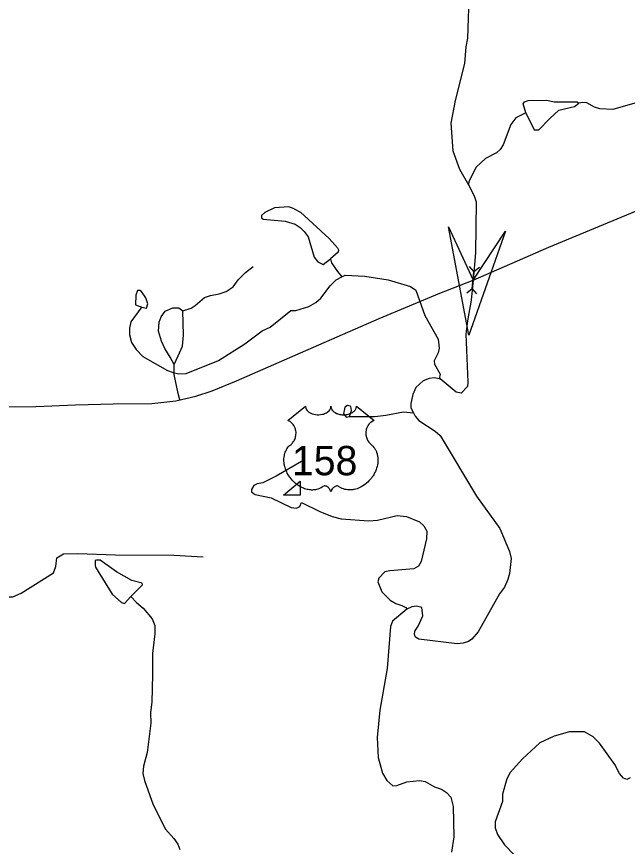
# Model space of a CAD drawing. Extents: x 2056842 to 2160602, y 826753 to 1016856.
# Drawn here: x 2086830 to 2091249, y 929883 to 935892 of the extents above; entities that cross this region are included whole.
import ezdxf

# ---------------------------------------------------------------- set-up
doc = ezdxf.new("R2010")
doc.units = 0
for name, color, linetype in [('Exist Hydrographic Creek Single Shore', 7, 'Continuous'), ('Exist Hydrographic Misc Water Feature', 7, 'Continuous'), ('Exist Hydrographic Pond Under 1500 Sq Ft', 7, 'Continuous'), ('Exist Road Non-System Type 51', 7, 'Continuous'), ('Exist Road Primary US Attributed', 7, 'Continuous'), ('Exist Road Primary US Shield CELL', 7, 'Continuous'), ('Exist Road Primary US Shield Number Label', 7, 'Continuous'), ('Exist Road Secondary Structure Culvert Attributed CELL', 7, 'Continuous'), ('Exist Road Secondary Structure Culvert CELL', 7, 'Continuous')]:
    doc.layers.add(name, color=color, linetype=linetype)

msp = doc.modelspace()

# ---------------------------------------------------------------- linework, layer by layer
at = {"layer": 'Exist Hydrographic Creek Single Shore'}
for points in [[(2090123.3, 936204), (2090103.7, 936095.8), (2090092.6, 935735.7), (2090078.8, 935671.7), (2090069.4, 935551.8), (2090002.2, 935283.5), (2089970.5, 935119.4), (2089985.4, 934919.6), (2090033.5, 934787.7), (2090100.1, 934673.7)], [(2092247.7, 935376.8), (2092095.6, 935418.2), (2091939.7, 935413.8), (2091799.9, 935425.4), (2091739.6, 935441.1), (2091683.6, 935436.9), (2091587.8, 935394.6), (2091484.1, 935326.3), (2091420.1, 935298.1), (2091142.5, 935219.3), (2091050.4, 935223), (2091010.4, 935234.9), (2090954.2, 935266.6), (2090926.3, 935270.5), (2090898.3, 935264.5)], [(2090514.6, 935195.3), (2090494.3, 935259.3), (2090504.3, 935273.2), (2090530.2, 935283.4), (2090666.3, 935285.7), (2090718.2, 935273.9), (2090884.3, 935274.4), (2090898.3, 935264.5)], [(2090686.6, 935153.9), (2090752.5, 935214), (2090866.5, 935240.4), (2090898.3, 935264.5)], [(2090514.6, 935195.3), (2090440.6, 935159.1), (2090406.7, 935111), (2090349.3, 934962.8), (2090327.4, 934928.7), (2090301.3, 934904.6), (2090221.6, 934864.4), (2090155.8, 934802.2), (2090102.2, 934698), (2090100.2, 934674)], [(2090514.6, 935195.3), (2090574.9, 935071.5), (2090606.9, 935071.6), (2090686.6, 935153.9)], [(2090100.1, 934673.7), (2090140.4, 934594.1), (2090154.3, 934550.2), (2090149.8, 934180.5), (2090132.3, 933982.4), (2090117.5, 933837), (2090091.1, 933687.9), (2090079.3, 933592), (2090094.3, 933243.9), (2090092.7, 933212.1), (2090046.7, 933163.8), (2090010.8, 933171.8), (2089894.4, 933269.3), (2089886.5, 933269.2)], [(2089182.4, 934007.2), (2089206.4, 934019.3), (2089350.3, 934011.7), (2089518.5, 933984.2), (2089678.6, 933936.8), (2089718.6, 933910.9), (2089783.2, 933727.1), (2089879.8, 933555.4), (2089888, 933489.5), (2089880, 933457.5), (2089850.2, 933399.3), (2089852.3, 933375.3), (2089894.5, 933301.4), (2089886.5, 933269.4)], [(2089886.5, 933269.2), (2089850.5, 933275.2), (2089814.4, 933271), (2089770.4, 933254.8), (2089718.5, 933206.7), (2089696.8, 933154.6), (2089681, 933090.7), (2089681, 933058.8), (2089701.3, 933022.6)], [(2089701.3, 933022.6), (2089713.2, 932998.8), (2089739.5, 932966.7), (2089857.6, 932889.1), (2089893.7, 932857.2), (2090156.9, 932418.3), (2090325.7, 932184.8), (2090396.4, 932018.9), (2090408.4, 931967.1), (2090396.7, 931859.1), (2090384.9, 931815), (2090359.2, 931758.8), (2090323.1, 931712.6), (2090168.1, 931436.3), (2090124.3, 931384), (2090098.4, 931366.2), (2090060.4, 931353.9), (2090016.3, 931349.9), (2089740.4, 931382.8), (2089716.4, 931396.8), (2089708.3, 931417), (2089712.1, 931440.8), (2089736.1, 931477.1), (2089769.8, 931551.2), (2089761.6, 931613.1), (2089723.7, 931621.1), (2089689.5, 931616.9), (2089653.7, 931600.5)], [(2088891.4, 932372.4), (2089023.7, 932306.8), (2089113.9, 932271.1), (2089177.9, 932255.4), (2089377.8, 932240), (2089441.8, 932244.2), (2089583.7, 932278.5), (2089651.7, 932270.8), (2089745.9, 932233.1), (2089776, 932205.2), (2089798.1, 932165.2), (2089796.1, 932109.3), (2089756.7, 931945.1), (2089736.8, 931913), (2089704.9, 931893), (2089531, 931878.5), (2089494.9, 931870.3), (2089451.2, 931826.2), (2089443.2, 931798.2), (2089471.5, 931726.2), (2089531.6, 931666.4), (2089573.6, 931642.7), (2089617.7, 931626.8), (2089645.8, 931612.8), (2089653.8, 931600.8)], [(2089653.7, 931600.5), (2089549.9, 931514.4), (2089535.9, 931474.3), (2089510.9, 931170.4), (2089458.1, 930870.2), (2089438.5, 930670.1), (2089445, 930526), (2089477.4, 930412.1), (2089507.5, 930360.3), (2089551.7, 930320.3), (2089579.6, 930324.7), (2089653.7, 930350.7), (2089745.4, 930360.9), (2089785.6, 930353.2), (2089853.7, 930313.4), (2089903.6, 930297.6), (2089939.8, 930273.5), (2089971.9, 930239.7), (2089987.9, 930171.8), (2089992.9, 929951.9), (2089977.1, 929840)], [(2091269.3, 930379.8), (2091245.4, 930367.9), (2091221.3, 930377.6), (2091191.2, 930411.6), (2091159.1, 930475.6), (2091046.4, 930629.2), (2091000.5, 930677.1), (2090938.2, 930712.9), (2090830.3, 930712.5), (2090718.4, 930680), (2090614.7, 930631.6), (2090490.9, 930517.4), (2090401.2, 930417.2), (2090377.3, 930373.1), (2090345.8, 930260.9), (2090344.1, 930209), (2090292.4, 930060.8), (2090292.5, 930016.8), (2090308.6, 929968.9), (2090360.8, 929893), (2090433.1, 929819.3)]]:
    msp.add_lwpolyline(points, dxfattribs=at)
at = {"layer": 'Exist Hydrographic Misc Water Feature'}
for points in [[(2088836.9, 934500.1), (2088798.7, 934514), (2088694.8, 934505.7), (2088624.8, 934473.5), (2088601.1, 934451.4), (2088601.1, 934433.4), (2088612.9, 934425.4), (2088773.1, 934409.9), (2088845.1, 934388.1), (2088881.4, 934364.3), (2088909.2, 934334.4)], [(2088836.9, 934500.1), (2088883, 934476.3), (2089091.5, 934284.9), (2089151.6, 934217.1), (2089157.8, 934203.1), (2089155.7, 934185.2), (2089102, 934136.9)], [(2088909.2, 934334.4), (2088939.4, 934296.4), (2088983.9, 934148.6), (2089008.1, 934116.6), (2089048.1, 934096.8), (2089102, 934136.9)], [(2089102, 934136.9), (2089107.9, 934108.9), (2089152.2, 934045.2), (2089182.4, 934007.2)], [(2087735.1, 933788.7), (2087657.4, 933680.5), (2087645.7, 933636.5), (2087645.7, 933586.4), (2087661.9, 933532.5), (2087696, 933480.6), (2087744.3, 933430.7), (2087920.5, 933329.3), (2087962.5, 933313.4), (2088004.8, 933305.5), (2088056.6, 933307.8), (2088290.4, 933400.5), (2088481.9, 933521), (2088607.6, 933615.5), (2088665.6, 933643.7), (2088815.1, 933764.1), (2088851.2, 933764.2), (2088945.1, 933792.5), (2088995, 933820.6), (2089030.8, 933852.8), (2089098.5, 933941), (2089142.4, 933985.1), (2089182.4, 934007.2)], [(2089239.6, 932995.5), (2089421.5, 932996), (2089501.4, 933004.3), (2089629.4, 933030.7), (2089701.4, 933022.9)], [(2088890.6, 932670.4), (2088708.9, 932563.9), (2088611.1, 932515.5), (2088571.1, 932507.5), (2088547.1, 932495.3), (2088529.1, 932467.3), (2088529.3, 932451.3), (2088541.4, 932441.3)], [(2088541.4, 932441.3), (2088555.3, 932431.4), (2088671.4, 932407.7), (2088815.5, 932336.1), (2088855.5, 932332.4), (2088879.5, 932344.3), (2088891.4, 932372.4)], [(2087553.2, 931870.3), (2087434.9, 931955.9), (2087407, 931955.8), (2087398.8, 931951.8), (2087399, 931917.7)], [(2087399, 931917.7), (2087401.1, 931903.8), (2087521.7, 931710.1), (2087587.9, 931648.4), (2087609.8, 931640.5), (2087657.6, 931692.6)], [(2087657.6, 931692.6), (2087741.5, 931776.9), (2087737.4, 931788.9), (2087663.4, 931808.6), (2087553.2, 931870.3)], [(2087657.6, 931692.6), (2087697.8, 931648.7), (2087746, 931608.8), (2087810.2, 931531.1), (2087830.3, 931483.1), (2087830.5, 931423.1), (2087813, 931279.1), (2087813.5, 931127.1), (2087808.1, 930927.1), (2087798.3, 930851.1), (2087800.5, 930775.1), (2087775.1, 930563.1), (2087747.6, 930463), (2087743.7, 930410.9), (2087755.8, 930358.9), (2087818.4, 930183.2), (2087907, 930007.5), (2087967.2, 929939.7), (2087995.3, 929899.8), (2088011.5, 929859.8)]]:
    msp.add_lwpolyline(points, dxfattribs=at)
at = {"layer": 'Exist Hydrographic Pond Under 1500 Sq Ft'}
for points in [[(2087692.8, 933874.5), (2087691, 933804.3), (2087734.9, 933788.6)], [(2087764.9, 933854.6), (2087734.6, 933900.5), (2087720.7, 933908.3), (2087704.6, 933908.4), (2087692.8, 933874.5)], [(2087734.9, 933788.6), (2087768.9, 933780.7), (2087779, 933810.7), (2087764.9, 933854.6)], [(2089243.2, 933071.2), (2089224.9, 933075.2), (2089205, 933063.1), (2089197.3, 933027.2)], [(2089239.3, 932995.2), (2089253.1, 933039.5), (2089249, 933067.5), (2089243.2, 933071.2)], [(2089197.3, 933027.2), (2089195.2, 933017.1), (2089215.3, 932991.4), (2089239.3, 932995.2)], [(2088759.8, 932426), (2088882.6, 932528.5), (2088882.6, 932426.5), (2088759.8, 932426)]]:
    msp.add_lwpolyline(points, dxfattribs=at)
at = {"layer": 'Exist Road Non-System Type 51'}
for points in [[(2088031.7, 933760.2), (2088092.4, 933781), (2088121.2, 933800.2), (2088188.4, 933857.8), (2088233.1, 933872.2), (2088296.6, 933884.1), (2088346.2, 933901.7), (2088397.4, 933933.7), (2088434.1, 933984.9), (2088485.3, 934037.7), (2088541.3, 934082.5)], [(2087969.3, 933371.7), (2087940.5, 933425.7), (2087902.1, 933488.1), (2087878.1, 933541), (2087857.4, 933614.6), (2087860.6, 933678.6), (2087874.9, 933718.6), (2087905.3, 933758.6), (2087959.7, 933782.6), (2088004.5, 933782.6), (2088031.7, 933760.2)], [(2087969.3, 933371.7), (2087999.7, 933435.3), (2088030.1, 933504.1), (2088036.5, 933585.8), (2088031.7, 933760.2)], [(2088010.9, 933115.6), (2087999.7, 933162.1), (2087970.9, 933299.7), (2087969.3, 933371.7)], [(2086588.8, 931704.8), (2086733.9, 931690.9), (2086802.2, 931690.9), (2086863.3, 931716), (2087096.8, 931863.4), (2087113, 931908.4), (2087121.9, 931973.1), (2087170.4, 932001.8), (2087271.9, 932004.5), (2087545, 931993.7), (2087967.1, 931991.9), (2088180.9, 931979.4)]]:
    msp.add_lwpolyline(points, dxfattribs=at)
at = {"layer": 'Exist Road Primary US Attributed'}
msp.add_lwpolyline([(2086615, 933065.8), (2086754.5, 933066.2), (2086968.8, 933067.8), (2087255.8, 933080.6), (2087527.7, 933087), (2087808.3, 933091), (2087982.6, 933108.6), (2088126.5, 933143.8), (2088244.8, 933182.3), (2088420.7, 933254.3), (2088845.3, 933439.1), (2089452.5, 933704.2), (2089891.6, 933889.3), (2090132.3, 933982.4), (2090679.4, 934221.5), (2091273.8, 934469), (2091725.5, 934661), (2092051.7, 934805), (2092677.7, 935064.9), (2093273.6, 935314.1), (2093861.1, 935518.5), (2094214.5, 935609.7), (2094739.8, 935742.3), (2095477.5, 935930.9)], dxfattribs=at)
at = {"layer": 'Exist Road Primary US Shield CELL'}
msp.add_lwpolyline([(2088920.1, 933069.6), (2088920.4, 933064.2), (2088921.7, 933057.9), (2088922.7, 933054.7), (2088925.6, 933048.4), (2088930.5, 933041.1), (2088937.3, 933033.8), (2088945, 933027.5), (2088950.1, 933024.2), (2088958.9, 933019.5), (2088968.9, 933015.3), (2088979.9, 933012.1), (2088991.3, 933009.8), (2089003.6, 933008.5), (2089015.9, 933008.2), (2089029.1, 933009.2), (2089043.7, 933012), (2089050.4, 933013.8), (2089057.9, 933016.4), (2089064.9, 933019.2), (2089072.6, 933023.3), (2089078.8, 933027.3), (2089083.6, 933030.8), (2089090.4, 933037.3), (2089095.8, 933044.1), (2089098.1, 933047.9), (2089100.1, 933051.5), (2089102.8, 933059.3), (2089103.6, 933062.7), (2089104.1, 933069.8), (2089104.5, 933063.8), (2089105.2, 933060.1), (2089106.1, 933056.5), (2089107.7, 933052.6), (2089110.4, 933047.1), (2089113.4, 933042.6), (2089119.2, 933035.8), (2089122.7, 933032.5), (2089126, 933029.8), (2089134.7, 933023.8), (2089144.9, 933018.6), (2089150, 933016.4), (2089155.1, 933014.6), (2089161.7, 933012.6), (2089168.4, 933011), (2089175.1, 933009.9), (2089181.9, 933008.9), (2089188.9, 933008.4), (2089194.6, 933008.2), (2089201.6, 933008.3), (2089208.1, 933008.7), (2089214.7, 933009.4), (2089222, 933010.7), (2089227.8, 933011.9), (2089235.6, 933014), (2089242.5, 933016.5), (2089248.7, 933019.2), (2089256.7, 933023.3), (2089263.1, 933027.4), (2089267.8, 933031.2), (2089273.5, 933036.3), (2089278.8, 933042.5), (2089281.9, 933047), (2089284.1, 933051.6), (2089286.1, 933056.5), (2089287.4, 933061.6), (2089288, 933066.1), (2089288.1, 933070), (2089416.7, 932967.5), (2089413.7, 932966.4), (2089406.7, 932962.9), (2089401.2, 932959.7), (2089392.3, 932953.4), (2089388.5, 932950), (2089384.7, 932946.4), (2089381.2, 932942.6), (2089378.1, 932939.1), (2089374.4, 932933.9), (2089371.1, 932928.7), (2089367.8, 932923), (2089365.4, 932918.1), (2089361.5, 932907.8), (2089359.6, 932901.2), (2089358.4, 932895.7), (2089356.8, 932884.2), (2089356.5, 932878.7), (2089356.5, 932873.3), (2089356.8, 932867.6), (2089357.3, 932862.2), (2089358.3, 932856.5), (2089359.2, 932851.5), (2089360.8, 932845.3), (2089363.1, 932838.2), (2089365.9, 932831.2), (2089371.8, 932820.1), (2089379.3, 932808.7), (2089384.7, 932802.3), (2089390, 932796.8), (2089398, 932790.1), (2089402.3, 932786.3), (2089407.2, 932781.4), (2089415.2, 932772.1), (2089418.5, 932767.6), (2089421.8, 932762.7), (2089424.9, 932757.6), (2089427.9, 932752.1), (2089430.3, 932747.4), (2089434.8, 932736.3), (2089438.1, 932725.6), (2089439.7, 932720), (2089442.1, 932707.4), (2089443, 932701.2), (2089444, 932688.8), (2089444, 932674), (2089442.8, 932659.8), (2089440.2, 932643.3), (2089438, 932633.5), (2089434.6, 932622), (2089431.3, 932612), (2089425.5, 932597.4), (2089420.3, 932586.7), (2089413.5, 932574.3), (2089408.9, 932566.7), (2089403.5, 932558.7), (2089396.7, 932549.4), (2089388.8, 932539.5), (2089379.3, 932529.1), (2089371.6, 932521.4), (2089361.6, 932512.5), (2089355.5, 932507.5), (2089346.9, 932500.9), (2089335, 932493), (2089323.3, 932486.3), (2089313.4, 932481.2), (2089304.6, 932477.4), (2089293.2, 932473), (2089274.2, 932467.8), (2089267.3, 932466.4), (2089259.1, 932465.1), (2089251.4, 932464.4), (2089244, 932463.9), (2089234, 932463.9), (2089224, 932464.7), (2089214.6, 932466.1), (2089204.8, 932468.1), (2089194.5, 932471.1), (2089185.2, 932474.8), (2089175.8, 932479.4), (2089159.9, 932489.5), (2089155.3, 932491.9), (2089152.7, 932492.6), (2089146.6, 932492.9), (2089140.8, 932491.7), (2089134.9, 932489.3), (2089131.3, 932487.4), (2089126.6, 932484.3), (2089122.9, 932481.4), (2089118.5, 932477.2), (2089115.5, 932473.7), (2089113.2, 932471), (2089108.7, 932463.9), (2089107.1, 932460.6), (2089105.4, 932456.3), (2089104, 932449.9), (2089101.9, 932457.9), (2089099.6, 932463.2), (2089096.8, 932467.8), (2089094, 932471.8), (2089089.5, 932477), (2089085.5, 932480.9), (2089080.6, 932484.8), (2089075.5, 932487.9), (2089071.3, 932490.1), (2089067.5, 932491.5), (2089062.9, 932492.7), (2089059.1, 932493), (2089056, 932492.9), (2089051.7, 932491.9), (2089045.9, 932487.7), (2089040.4, 932483.9), (2089034.4, 932480.2), (2089027.2, 932476.4), (2089022, 932474), (2089015.8, 932471.5), (2089008.5, 932469.1), (2089000.6, 932467), (2088992.4, 932465.4), (2088985.3, 932464.3), (2088977.6, 932463.6), (2088970.7, 932463.4), (2088963.5, 932463.5), (2088956.8, 932464), (2088948.9, 932464.7), (2088939.2, 932466.1), (2088931.2, 932468), (2088922.7, 932470.2), (2088913.9, 932473), (2088904.6, 932476.5), (2088892.9, 932481.6), (2088884.8, 932485.8), (2088871.9, 932493.2), (2088856.9, 932503.6), (2088845.5, 932512.8), (2088837.2, 932520.3), (2088825, 932532.8), (2088817.8, 932540.9), (2088806.5, 932555.5), (2088799.3, 932566.1), (2088794.6, 932573.8), (2088787.8, 932586.3), (2088784, 932594.1), (2088779.2, 932605.5), (2088775.4, 932615.9), (2088772.2, 932625.8), (2088770.5, 932632.1), (2088768, 932643.1), (2088766.5, 932650.9), (2088765.1, 932661.6), (2088764.3, 932673), (2088764.2, 932683.4), (2088764.4, 932692), (2088765.4, 932702.1), (2088767.1, 932712.9), (2088769.2, 932722.1), (2088771, 932728.7), (2088773.8, 932736.7), (2088777.4, 932745.6), (2088781.6, 932754.1), (2088785.7, 932761.2), (2088790.8, 932768.8), (2088795.8, 932775.2), (2088802.4, 932782.4), (2088809.2, 932788.9), (2088815.5, 932794), (2088822.9, 932801.3), (2088826.8, 932805.7), (2088831.4, 932811.9), (2088835.2, 932817.6), (2088838.1, 932822.7), (2088842, 932830.2), (2088844.4, 932835.8), (2088847.4, 932844.5), (2088848.8, 932850.5), (2088850.4, 932858.4), (2088851.3, 932865.7), (2088851.7, 932874.9), (2088851.5, 932882.5), (2088850.5, 932891.4), (2088848.8, 932899.9), (2088846.8, 932907.4), (2088843.6, 932915.9), (2088840.7, 932922.1), (2088835.8, 932930.6), (2088830.3, 932938.4), (2088824.6, 932944.8), (2088818.9, 932950.5), (2088813.5, 932954.7), (2088808.3, 932958.4), (2088801.7, 932962.4), (2088795.4, 932965.5), (2088791.5, 932967.1)], close=True, dxfattribs=at)
at = {"layer": 'Exist Road Secondary Structure Culvert Attributed CELL'}
msp.add_lwpolyline([(2090367.1, 934338.4), (2090102, 933583.6), (2089954.1, 934369.8), (2090132.3, 933982.4)], close=True, dxfattribs=at)
at = {"layer": 'Exist Road Secondary Structure Culvert CELL'}
for p, q in [((2090104.4, 934080.8), (2090137.9, 934042.7)), ((2090126.8, 933922.2), (2090137.9, 934042.7)), ((2090177.8, 934074), (2090137.9, 934042.7)), ((2090086.8, 933890.9), (2090126.8, 933922.2)), ((2090160.3, 933884.1), (2090126.8, 933922.2))]:
    msp.add_line(p, q, dxfattribs=at)

# ---------------------------------------------------------------- texts
at = {"layer": 'Exist Road Primary US Shield Number Label'}
msp.add_text('158', height=212.5, dxfattribs=at).set_placement((2088821.3, 932570.2))

doc.saveas('drawing.dxf')
